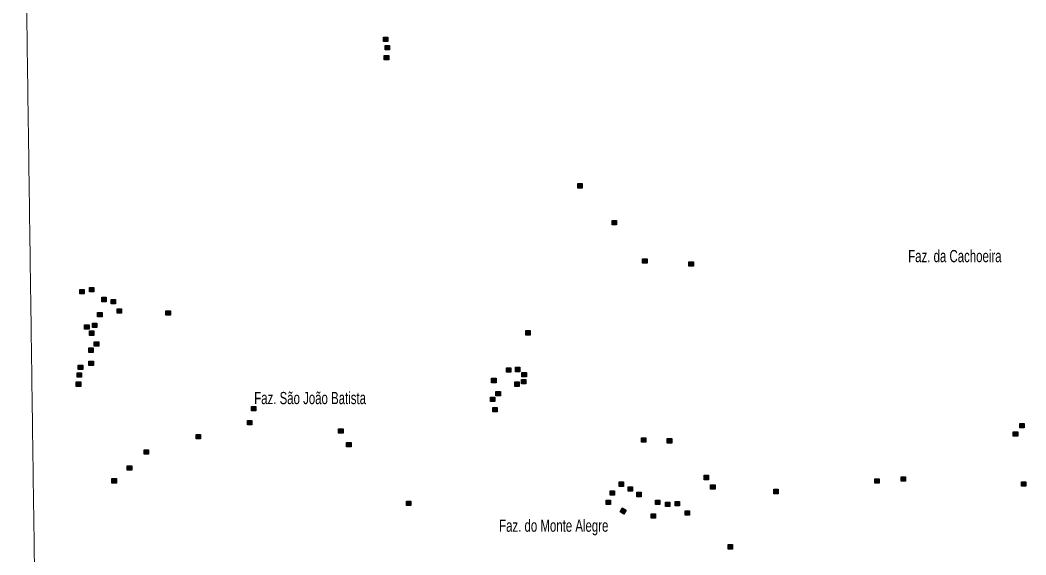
# Model space of a CAD drawing. Extents: x 265.7 to 292.1, y 7676.2 to 7704.2.
# Drawn here: x 265.72 to 272.31, y 7697.19 to 7700.7 of the extents above; entities that cross this region are included whole.
import ezdxf

# ---------------------------------------------------------------- set-up
doc = ezdxf.new("R2010")
doc.units = 0
doc.header["$LTSCALE"] = 0.032
doc.layers.add('2', color=7, linetype='Continuous', lineweight=25)
doc.layers.add('63', color=7, linetype='Continuous', lineweight=13)
doc.layers.add('61', color=7, linetype='Continuous')

msp = doc.modelspace()

# ---------------------------------------------------------------- hatches: boundary and pattern name
at = {"layer": '2'}
for points in [[(268.0996, 7700.5865), (268.1286, 7700.5865), (268.1286, 7700.5575), (268.0996, 7700.5575)], [(268.11, 7700.5323), (268.139, 7700.5323), (268.139, 7700.5033), (268.11, 7700.5033)], [(268.1045, 7700.4662), (268.1335, 7700.4662), (268.1335, 7700.4372), (268.1045, 7700.4372)], [(269.3732, 7699.626), (269.4022, 7699.626), (269.4022, 7699.597), (269.3732, 7699.597)], [(269.5977, 7699.3844), (269.6267, 7699.3844), (269.6267, 7699.3554), (269.5977, 7699.3554)], [(269.7977, 7699.133), (269.8267, 7699.133), (269.8267, 7699.104), (269.7977, 7699.104)], [(270.1011, 7699.1135), (270.1301, 7699.1135), (270.1301, 7699.0845), (270.1011, 7699.0845)], [(266.1094, 7698.9328), (266.1384, 7698.9328), (266.1384, 7698.9038), (266.1094, 7698.9038)], [(266.1723, 7698.9457), (266.2013, 7698.9457), (266.2013, 7698.9167), (266.1723, 7698.9167)], [(266.2538, 7698.8811), (266.2828, 7698.8811), (266.2828, 7698.8521), (266.2538, 7698.8521)], [(266.3143, 7698.8666), (266.3433, 7698.8666), (266.3433, 7698.8376), (266.3143, 7698.8376)], [(266.2256, 7698.781), (266.2546, 7698.781), (266.2546, 7698.752), (266.2256, 7698.752)], [(266.354, 7698.8052), (266.383, 7698.8052), (266.383, 7698.7762), (266.354, 7698.7762)], [(266.6735, 7698.7923), (266.7025, 7698.7923), (266.7025, 7698.7633), (266.6735, 7698.7633)], [(266.1925, 7698.7116), (266.2215, 7698.7116), (266.2215, 7698.6826), (266.1925, 7698.6826)], [(266.1408, 7698.7012), (266.1698, 7698.7012), (266.1698, 7698.6722), (266.1408, 7698.6722)], [(266.1723, 7698.66), (266.2013, 7698.66), (266.2013, 7698.631), (266.1723, 7698.631)], [(269.0325, 7698.6624), (269.0615, 7698.6624), (269.0615, 7698.6334), (269.0325, 7698.6334)], [(266.2038, 7698.5898), (266.2328, 7698.5898), (266.2328, 7698.5608), (266.2038, 7698.5608)], [(266.1683, 7698.5486), (266.1973, 7698.5486), (266.1973, 7698.5196), (266.1683, 7698.5196)], [(266.1691, 7698.463), (266.1981, 7698.463), (266.1981, 7698.434), (266.1691, 7698.434)], [(266.0908, 7698.3856), (266.1198, 7698.3856), (266.1198, 7698.3566), (266.0908, 7698.3566)], [(266.0989, 7698.4365), (266.1279, 7698.4365), (266.1279, 7698.4075), (266.0989, 7698.4075)], [(268.9051, 7698.4195), (268.9341, 7698.4195), (268.9341, 7698.3905), (268.9051, 7698.3905)], [(268.9647, 7698.4219), (268.9937, 7698.4219), (268.9937, 7698.3929), (268.9647, 7698.3929)], [(269.0068, 7698.3888), (269.0358, 7698.3888), (269.0358, 7698.3598), (269.0068, 7698.3598)], [(266.086, 7698.3258), (266.115, 7698.3258), (266.115, 7698.2968), (266.086, 7698.2968)], [(268.8081, 7698.3501), (268.8371, 7698.3501), (268.8371, 7698.3211), (268.8081, 7698.3211)], [(268.9599, 7698.3258), (268.9889, 7698.3258), (268.9889, 7698.2968), (268.9599, 7698.2968)], [(269.0034, 7698.3428), (269.0324, 7698.3428), (269.0324, 7698.3138), (269.0034, 7698.3138)], [(268.8364, 7698.263), (268.8654, 7698.263), (268.8654, 7698.234), (268.8364, 7698.234)], [(268.8001, 7698.2258), (268.8291, 7698.2258), (268.8291, 7698.1968), (268.8001, 7698.1968)], [(267.2344, 7698.166), (267.2634, 7698.166), (267.2634, 7698.137), (267.2344, 7698.137)], [(268.8155, 7698.1595), (268.8445, 7698.1595), (268.8445, 7698.1305), (268.8155, 7698.1305)], [(267.207, 7698.074), (267.236, 7698.074), (267.236, 7698.045), (267.207, 7698.045)], [(272.2689, 7698.0546), (272.2979, 7698.0546), (272.2979, 7698.0256), (272.2689, 7698.0256)], [(266.8707, 7697.9823), (266.8997, 7697.9823), (266.8997, 7697.9533), (266.8707, 7697.9533)], [(267.805, 7698.0189), (267.834, 7698.0189), (267.834, 7697.9899), (267.805, 7697.9899)], [(272.2268, 7697.9999), (272.2558, 7697.9999), (272.2558, 7697.9709), (272.2268, 7697.9709)], [(267.8575, 7697.9288), (267.8865, 7697.9288), (267.8865, 7697.8998), (267.8575, 7697.8998)], [(269.7895, 7697.9595), (269.8185, 7697.9595), (269.8185, 7697.9305), (269.7895, 7697.9305)], [(269.9591, 7697.9545), (269.9881, 7697.9545), (269.9881, 7697.9255), (269.9591, 7697.9255)], [(266.5306, 7697.882), (266.5596, 7697.882), (266.5596, 7697.853), (266.5306, 7697.853)], [(266.4201, 7697.7771), (266.4491, 7697.7771), (266.4491, 7697.7481), (266.4201, 7697.7481)], [(266.32, 7697.6924), (266.349, 7697.6924), (266.349, 7697.6634), (266.32, 7697.6634)], [(269.6427, 7697.6705), (269.6717, 7697.6705), (269.6717, 7697.6415), (269.6427, 7697.6415)], [(270.2011, 7697.7141), (270.2301, 7697.7141), (270.2301, 7697.6851), (270.2011, 7697.6851)], [(270.2431, 7697.6512), (270.2721, 7697.6512), (270.2721, 7697.6222), (270.2431, 7697.6222)], [(271.3197, 7697.6915), (271.3487, 7697.6915), (271.3487, 7697.6625), (271.3197, 7697.6625)], [(271.4915, 7697.7044), (271.5205, 7697.7044), (271.5205, 7697.6754), (271.4915, 7697.6754)], [(272.2802, 7697.6708), (272.3092, 7697.6708), (272.3092, 7697.6418), (272.2802, 7697.6418)], [(269.5838, 7697.6131), (269.6128, 7697.6131), (269.6128, 7697.5841), (269.5838, 7697.5841)], [(269.7032, 7697.6392), (269.7322, 7697.6392), (269.7322, 7697.6102), (269.7032, 7697.6102)], [(269.7589, 7697.6028), (269.7879, 7697.6028), (269.7879, 7697.5738), (269.7589, 7697.5738)], [(270.6564, 7697.6221), (270.6854, 7697.6221), (270.6854, 7697.5931), (270.6564, 7697.5931)], [(268.2497, 7697.5455), (268.2787, 7697.5455), (268.2787, 7697.5165), (268.2497, 7697.5165)], [(269.5588, 7697.5519), (269.5878, 7697.5519), (269.5878, 7697.5229), (269.5588, 7697.5229)], [(269.8808, 7697.5511), (269.9098, 7697.5511), (269.9098, 7697.5221), (269.8808, 7697.5221)], [(269.9469, 7697.539), (269.9759, 7697.539), (269.9759, 7697.51), (269.9469, 7697.51)], [(270.0107, 7697.5431), (270.0397, 7697.5431), (270.0397, 7697.5141), (270.0107, 7697.5141)], [(269.6643, 7697.5), (269.6893, 7697.4854), (269.6747, 7697.4603), (269.6497, 7697.4749)], [(269.8525, 7697.4615), (269.8815, 7697.4615), (269.8815, 7697.4325), (269.8525, 7697.4325)], [(270.076, 7697.4816), (270.105, 7697.4816), (270.105, 7697.4526), (270.076, 7697.4526)], [(270.3576, 7697.2598), (270.3866, 7697.2598), (270.3866, 7697.2308), (270.3576, 7697.2308)]]:
    msp.add_hatch(color=256, dxfattribs=at).paths.add_polyline_path(points)

# ---------------------------------------------------------------- linework, layer by layer
for points in [[(268.0996, 7700.5865), (268.1286, 7700.5865), (268.1286, 7700.5575), (268.0996, 7700.5575)], [(268.11, 7700.5323), (268.139, 7700.5323), (268.139, 7700.5033), (268.11, 7700.5033)], [(268.1045, 7700.4662), (268.1335, 7700.4662), (268.1335, 7700.4372), (268.1045, 7700.4372)], [(269.3732, 7699.626), (269.4022, 7699.626), (269.4022, 7699.597), (269.3732, 7699.597)], [(269.5977, 7699.3844), (269.6267, 7699.3844), (269.6267, 7699.3554), (269.5977, 7699.3554)], [(269.7977, 7699.133), (269.8267, 7699.133), (269.8267, 7699.104), (269.7977, 7699.104)], [(270.1011, 7699.1135), (270.1301, 7699.1135), (270.1301, 7699.0845), (270.1011, 7699.0845)], [(266.1094, 7698.9328), (266.1384, 7698.9328), (266.1384, 7698.9038), (266.1094, 7698.9038)], [(266.1723, 7698.9457), (266.2013, 7698.9457), (266.2013, 7698.9167), (266.1723, 7698.9167)], [(266.2538, 7698.8811), (266.2828, 7698.8811), (266.2828, 7698.8521), (266.2538, 7698.8521)], [(266.3143, 7698.8666), (266.3433, 7698.8666), (266.3433, 7698.8376), (266.3143, 7698.8376)], [(266.2256, 7698.781), (266.2546, 7698.781), (266.2546, 7698.752), (266.2256, 7698.752)], [(266.354, 7698.8052), (266.383, 7698.8052), (266.383, 7698.7762), (266.354, 7698.7762)], [(266.6735, 7698.7923), (266.7025, 7698.7923), (266.7025, 7698.7633), (266.6735, 7698.7633)], [(266.1925, 7698.7116), (266.2215, 7698.7116), (266.2215, 7698.6826), (266.1925, 7698.6826)], [(266.1408, 7698.7012), (266.1698, 7698.7012), (266.1698, 7698.6722), (266.1408, 7698.6722)], [(266.1723, 7698.66), (266.2013, 7698.66), (266.2013, 7698.631), (266.1723, 7698.631)], [(269.0325, 7698.6624), (269.0615, 7698.6624), (269.0615, 7698.6334), (269.0325, 7698.6334)], [(266.2038, 7698.5898), (266.2328, 7698.5898), (266.2328, 7698.5608), (266.2038, 7698.5608)], [(266.1683, 7698.5486), (266.1973, 7698.5486), (266.1973, 7698.5196), (266.1683, 7698.5196)], [(266.1691, 7698.463), (266.1981, 7698.463), (266.1981, 7698.434), (266.1691, 7698.434)], [(266.0908, 7698.3856), (266.1198, 7698.3856), (266.1198, 7698.3566), (266.0908, 7698.3566)], [(266.0989, 7698.4365), (266.1279, 7698.4365), (266.1279, 7698.4075), (266.0989, 7698.4075)], [(268.9051, 7698.4195), (268.9341, 7698.4195), (268.9341, 7698.3905), (268.9051, 7698.3905)], [(268.9647, 7698.4219), (268.9937, 7698.4219), (268.9937, 7698.3929), (268.9647, 7698.3929)], [(269.0068, 7698.3888), (269.0358, 7698.3888), (269.0358, 7698.3598), (269.0068, 7698.3598)], [(266.086, 7698.3258), (266.115, 7698.3258), (266.115, 7698.2968), (266.086, 7698.2968)], [(268.8081, 7698.3501), (268.8371, 7698.3501), (268.8371, 7698.3211), (268.8081, 7698.3211)], [(268.9599, 7698.3258), (268.9889, 7698.3258), (268.9889, 7698.2968), (268.9599, 7698.2968)], [(269.0034, 7698.3428), (269.0324, 7698.3428), (269.0324, 7698.3138), (269.0034, 7698.3138)], [(268.8364, 7698.263), (268.8654, 7698.263), (268.8654, 7698.234), (268.8364, 7698.234)], [(268.8001, 7698.2258), (268.8291, 7698.2258), (268.8291, 7698.1968), (268.8001, 7698.1968)], [(267.2344, 7698.166), (267.2634, 7698.166), (267.2634, 7698.137), (267.2344, 7698.137)], [(268.8155, 7698.1595), (268.8445, 7698.1595), (268.8445, 7698.1305), (268.8155, 7698.1305)], [(267.207, 7698.074), (267.236, 7698.074), (267.236, 7698.045), (267.207, 7698.045)], [(272.2689, 7698.0546), (272.2979, 7698.0546), (272.2979, 7698.0256), (272.2689, 7698.0256)], [(266.8707, 7697.9823), (266.8997, 7697.9823), (266.8997, 7697.9533), (266.8707, 7697.9533)], [(267.805, 7698.0189), (267.834, 7698.0189), (267.834, 7697.9899), (267.805, 7697.9899)], [(272.2268, 7697.9999), (272.2558, 7697.9999), (272.2558, 7697.9709), (272.2268, 7697.9709)], [(267.8575, 7697.9288), (267.8865, 7697.9288), (267.8865, 7697.8998), (267.8575, 7697.8998)], [(269.7895, 7697.9595), (269.8185, 7697.9595), (269.8185, 7697.9305), (269.7895, 7697.9305)], [(269.9591, 7697.9545), (269.9881, 7697.9545), (269.9881, 7697.9255), (269.9591, 7697.9255)], [(266.5306, 7697.882), (266.5596, 7697.882), (266.5596, 7697.853), (266.5306, 7697.853)], [(266.4201, 7697.7771), (266.4491, 7697.7771), (266.4491, 7697.7481), (266.4201, 7697.7481)], [(266.32, 7697.6924), (266.349, 7697.6924), (266.349, 7697.6634), (266.32, 7697.6634)], [(269.6427, 7697.6705), (269.6717, 7697.6705), (269.6717, 7697.6415), (269.6427, 7697.6415)], [(270.2011, 7697.7141), (270.2301, 7697.7141), (270.2301, 7697.6851), (270.2011, 7697.6851)], [(270.2431, 7697.6512), (270.2721, 7697.6512), (270.2721, 7697.6222), (270.2431, 7697.6222)], [(271.3197, 7697.6915), (271.3487, 7697.6915), (271.3487, 7697.6625), (271.3197, 7697.6625)], [(271.4915, 7697.7044), (271.5205, 7697.7044), (271.5205, 7697.6754), (271.4915, 7697.6754)], [(272.2802, 7697.6708), (272.3092, 7697.6708), (272.3092, 7697.6418), (272.2802, 7697.6418)], [(269.5838, 7697.6131), (269.6128, 7697.6131), (269.6128, 7697.5841), (269.5838, 7697.5841)], [(269.7032, 7697.6392), (269.7322, 7697.6392), (269.7322, 7697.6102), (269.7032, 7697.6102)], [(269.7589, 7697.6028), (269.7879, 7697.6028), (269.7879, 7697.5738), (269.7589, 7697.5738)], [(270.6564, 7697.6221), (270.6854, 7697.6221), (270.6854, 7697.5931), (270.6564, 7697.5931)], [(268.2497, 7697.5455), (268.2787, 7697.5455), (268.2787, 7697.5165), (268.2497, 7697.5165)], [(269.5588, 7697.5519), (269.5878, 7697.5519), (269.5878, 7697.5229), (269.5588, 7697.5229)], [(269.8808, 7697.5511), (269.9098, 7697.5511), (269.9098, 7697.5221), (269.8808, 7697.5221)], [(269.9469, 7697.539), (269.9759, 7697.539), (269.9759, 7697.51), (269.9469, 7697.51)], [(270.0107, 7697.5431), (270.0397, 7697.5431), (270.0397, 7697.5141), (270.0107, 7697.5141)], [(269.6643, 7697.5), (269.6893, 7697.4854), (269.6747, 7697.4603), (269.6497, 7697.4749)], [(269.8525, 7697.4615), (269.8815, 7697.4615), (269.8815, 7697.4325), (269.8525, 7697.4325)], [(270.076, 7697.4816), (270.105, 7697.4816), (270.105, 7697.4526), (270.076, 7697.4526)], [(270.3576, 7697.2598), (270.3866, 7697.2598), (270.3866, 7697.2308), (270.3576, 7697.2308)]]:
    msp.add_lwpolyline(points, close=True, dxfattribs=at)
at = {"layer": '63'}
msp.add_spline([(266.1055, 7676.1764), (266.0976, 7676.7414), (266.0896, 7677.3064), (266.0817, 7677.8713), (266.0737, 7678.4363), (266.0658, 7679.0013), (266.0578, 7679.5663), (266.0499, 7680.1313), (266.0419, 7680.6963), (266.034, 7681.2613), (266.026, 7681.8263), (266.0181, 7682.3913), (266.0102, 7682.9563), (266.0022, 7683.5212), (265.9943, 7684.0862), (265.9864, 7684.6512), (265.9785, 7685.2162), (265.9705, 7685.7812), (265.9626, 7686.3462), (265.9547, 7686.9112), (265.9468, 7687.4762), (265.9389, 7688.0411), (265.9309, 7688.6061), (265.923, 7689.1711), (265.9151, 7689.7361), (265.9072, 7690.3011), (265.8993, 7690.8661), (265.8914, 7691.4311), (265.8835, 7691.996), (265.8756, 7692.561), (265.8677, 7693.126), (265.8598, 7693.691), (265.8519, 7694.256), (265.844, 7694.821), (265.8361, 7695.3859), (265.8282, 7695.9509), (265.8203, 7696.5159), (265.8124, 7697.0809), (265.8045, 7697.6459), (265.7967, 7698.2108), (265.7888, 7698.7758), (265.7809, 7699.3408), (265.773, 7699.9058), (265.7651, 7700.4708), (265.7573, 7701.0357), (265.7494, 7701.6007), (265.7415, 7702.1657), (265.7337, 7702.7307), (265.7258, 7703.2957), (265.7179, 7703.8606)], degree=3, dxfattribs=at)

# ---------------------------------------------------------------- texts
at = {"layer": '61', "width": 0.7}
for s, p in [('Faz. da Cachoeira', (271.5379, 7699.111)), ('Faz. São João Batista', (267.252, 7698.1805)), ('Faz. do Monte Alegre', (268.8571, 7697.3441))]:
    msp.add_text(s, height=0.08, dxfattribs=at).set_placement(p)

doc.saveas('drawing.dxf')
